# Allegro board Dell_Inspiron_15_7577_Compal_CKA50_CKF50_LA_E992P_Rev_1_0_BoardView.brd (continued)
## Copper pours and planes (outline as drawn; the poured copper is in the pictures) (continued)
N31436196 on TOP (solid shape): 160.6,131.6 160.75,131.56 160.9,131.6 160.91,131.6 161.65,131.6 161.71,131.54 161.71,130.9 161.65,130.84 160.3,130.84 160.21,130.85 160.12,130.84 159.49,130.84 159.42,130.9 159.42,131.54 159.49,131.6 160.59,131.6
N31436215 on TOP (solid shape): 160.21,130.19 160.3,130.2 160.44,130.2 160.5,130.14 160.5,129.52 160.82,129.2 160.82,128.93 160.68,128.79 160.44,128.79 160.29,128.94 160.29,129.18 160.03,129.44 159.49,129.44 159.42,129.5 159.42,130.14 159.49,130.2 160.12,130.2
N31436215 on BOTTOM (solid shape): 160.82,129.19 160.82,128.93 160.48,128.6 160.48,127.87 160.39,127.78 160.25,127.78 160.16,127.87 160.16,128.78 160.31,128.93 160.31,129.25 160.38,129.31 160.69,129.31
N31436218 on TOP (solid shape): 161.71,130.14 161.71,129.5 161.46,129.25 161.46,128.93 161.33,128.81 161.06,128.81 160.95,128.92 160.95,129.25 160.63,129.57 160.63,130.14 160.69,130.2 161.65,130.2
N31439632 on BOTTOM (solid shape): 115.42,121.76 115.42,119.85 115.16,119.6 114.53,119.6 114.4,119.73 114.4,121.82 114.47,121.88 115.29,121.88
N31439653 on BOTTOM (solid shape): 117.15,120.36 118.21,120.36 118.28,120.3 118.28,120.11 118.15,119.98 116.88,119.98 116.79,119.89 116.79,119.89 116.71,119.83 116.65,119.75 116.55,119.65 115.91,119.65 115.88,119.69 115.88,120.56 115.94,120.61 116.89,120.61
N31439658 on BOTTOM (solid shape): 116.7,121.81 116.93,121.81 117.36,121.38 118.15,121.38 118.28,121.25 118.28,121.12 118.15,121 116.82,121 116.72,120.9 116.05,120.9 116,120.95 116,121.77 116.05,121.82 116.69,121.82
N31452288 on BOTTOM (solid shape): 115.36,129.76 115.36,127.73 115.23,127.6 114.59,127.6 114.47,127.73 114.47,129.82 114.53,129.89 115.23,129.89
N31494164 on BOTTOM (solid shape): 169.93,130.35 169.93,129.53 169.8,129.4 167.91,129.4 167.68,129.17 167.39,129.17 167.23,129.33 167.23,129.58 167.62,129.97 167.62,130.33 167.68,130.39 169.88,130.39
N31494196 on BOTTOM (solid shape): 168.63,128.93 168.63,128.36 169.15,127.84 169.15,126.49 169.07,126.41 168.93,126.41 168.86,126.49 168.86,127.45 168.44,127.86 168.43,127.89 168.43,128.03 168.18,128.28 167.68,128.28 167.65,128.31 167.65,128.94 167.71,129 168.57,129
N31494209 on BOTTOM (solid shape): 169.9,128.93 169.9,126.71 169.6,126.41 169.44,126.41 169.36,126.5 169.36,127.83 168.89,128.3 168.89,128.93 168.95,129 169.84,129
N31528975 on BOTTOM (solid shape): 117.48,129.06 118.34,129.06 118.4,129 118.4,128.81 118.34,128.74 117.54,128.74 117.44,128.64 117.42,128.63 117.15,128.63 116.96,128.63 116.69,128.36 116.69,127.73 116.6,127.64 116,127.64 115.94,127.7 115.94,128.58 116.1,128.74 116.62,128.74 116.79,128.91 116.79,129.07 116.87,129.15 117.39,129.15
N31528977 on BOTTOM (solid shape): 118.47,129.95 118.47,129.89 118.34,129.76 117.58,129.76 117.12,129.29 116.83,129.29 116.66,129.12 116.66,128.96 116.62,128.92 116.01,128.92 115.93,129 115.93,129.82 116,129.89 116.01,129.89 116.09,129.97 117.28,129.97 117.39,130.08 118.34,130.08
N134148044 on BOTTOM (solid shape): outline of 83 points within 291.44,9.36 295.14,12.38
N134208615 on BOTTOM (solid shape): 369.42,119.03 369.42,116.56 369.42,116.56 369.42,116.17 369.23,115.98 368.59,115.98 368.21,116.36 368.21,119.03 368.28,119.09 369.36,119.09

Small or netless copper shapes (teardrops, artwork), in the pictures only: 40 on TOP, 183 on BOTTOM, 5 on IN1, 2 on IN2, 2 on IN3, 2 on IN4, 3 on IN5

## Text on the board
Ref Des/Silkscreen Bottom: H5 | HF
User.Comments: CR_1_1 | CR_1_2 | LA-E992P | 2017-07-17 | 2018-07-17 | CKA50/CKF50 | crazy
Ref Des/Silkscreen Top: H3 | H1 | H2 | H4 | H5 | H7 | H8 | H9 | H10 | H11 | H15 | H14 | H17 | H19 | H18 | H16 | HF
IN4: IN4
GND3: GND3
IN5: IN5
GND4: GND4
BODY_CENTER: L7 | L8 | L9 | L10 | L11 | L12 | GND2 | GND4 | BOT
User.40: IMPEDANCE
User.44: trace Width | Width/space | 5.7mil | 8.4mil | 6.8mil | 5.5mil | 3.8mil | 4.9mil | 5.4mil | 4.7 / 3.5 | 4.1 / 3.5 | 5.8 / 5 | 5.5 / 4.5 | 3.8 / 3.5 | 5.5 / 5.5 | 5.5 / 6.5 | 3.8 / 4 | 4.4 / 6.8 | 3.5 / 6.7 | L9/L11 | L2/L4 | L4/L6 | L6/L9 | L11 | L2 | L6/L8 | 1_36mm-EM370D_1086_1V1-12L_4mil_161129 | L1-TOP | L2-GND1 | L3-IN1 | L4-GND2 | L5-IN2 | L6-VCC | L7-IN3 | L8-IN4 | L9-GND3 | L10-IN5 | L11-GND4 | L12-BOT | LAYER | NAME | STACKUP: 12 LAYER | 40 ohm | 45 ohm | THICKNESS=1.36mm | 50 ohm | 80 ohm | 85 ohm | 88 ohm | 90 ohm | 100 ohm | Ref
User.45: FIGURE | SIZE | 8.0 | 22.0 | 28.0 | 35.0 | 110.0 | 118.0 | 130.0 | 146.0 | 157.0 | 40.0 | 43.0 | 45.0 | 63.0 | 65.0 | 177.0 | 49.0x28.0 | 55.0x24.0 | 55.0x28.0 | 63.0x24.0 | 67.0x24.0 | 67.0x28.0 | 67.0x39.0 | 75.0x28.0 | 98.0x24.0 | 98.0x39.0 | 130.0x24.0 | 134.0x110.0 | 33.0x28.0 | DRILL CHART: TOP to BOTTOM | ALL UNITS ARE IN MILS | TOLERANCE | +3.0/-3.0 | +2.0/-2.0 | PLATED | NON-PLATED | QTY | 10011 | 19 | 42 | 8 | 11 | 2 | 4 | 1 | 7 | 6
